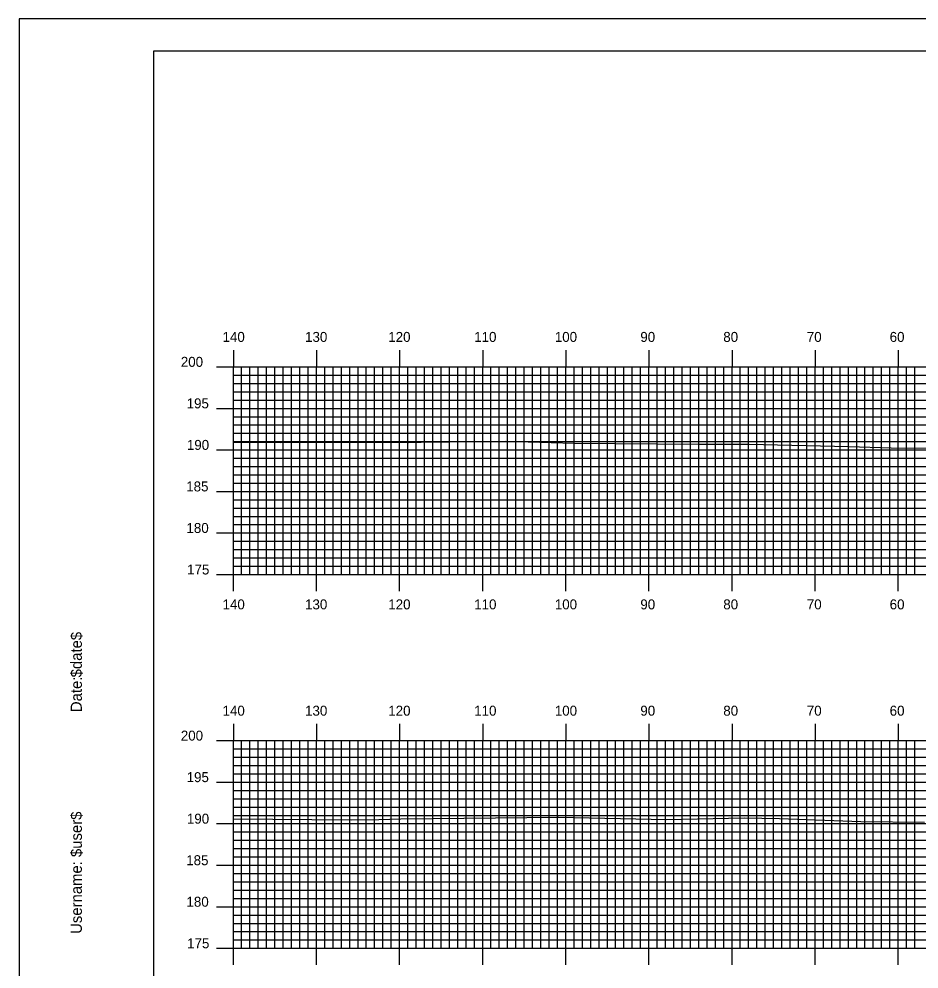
# Model space of a CAD drawing. Extents: x 1797994 to 1798337, y 442591 to 442811.
# Drawn here: x 1797994.2 to 1798102.5, y 442696.2 to 442810.5 of the extents above; entities that cross this region are included whole.
import ezdxf

# ---------------------------------------------------------------- set-up
doc = ezdxf.new("R2010")
doc.units = 0
for name, color, linetype in [('BORDER', 7, 'Continuous'), ('H_V ANNOTATION', 7, 'Continuous'), ('MAJOR', 7, 'Continuous'), ('MINOR', 7, 'Continuous'), ('PLOT BOUNDARY', 7, 'Continuous'), ('S_Roadway_Centerline', 7, 'Continuous')]:
    doc.layers.add(name, color=color, linetype=linetype)

msp = doc.modelspace()

# ---------------------------------------------------------------- linework, layer by layer
at = {"layer": 'BORDER'}
msp.add_lwpolyline([(1798010.36, 442596.67), (1798330.36, 442596.67), (1798330.36, 442806.67), (1798010.36, 442806.67)], close=True, dxfattribs=at)
at = {"layer": 'MAJOR'}
for p, q in [((1798019.96, 442770.67), (1798019.96, 442768.67)), ((1798029.96, 442770.67), (1798029.96, 442768.67)), ((1798039.96, 442770.67), (1798039.96, 442768.67)), ((1798049.96, 442770.67), (1798049.96, 442768.67)), ((1798059.96, 442770.67), (1798059.96, 442768.67)), ((1798069.96, 442770.67), (1798069.96, 442768.67)), ((1798079.96, 442770.67), (1798079.96, 442768.67)), ((1798089.96, 442770.67), (1798089.96, 442768.67)), ((1798099.96, 442770.67), (1798099.96, 442768.67)), ((1798017.95, 442768.67), (1798019.96, 442768.67)), ((1798019.96, 442768.67), (1798299.96, 442768.67)), ((1798019.96, 442743.67), (1798019.96, 442768.67)), ((1798019.96, 442743.67), (1798019.96, 442768.67)), ((1798019.96, 442768.67), (1798299.96, 442768.67)), ((1798029.96, 442743.67), (1798029.96, 442768.67)), ((1798039.96, 442743.67), (1798039.96, 442768.67)), ((1798049.96, 442743.67), (1798049.96, 442768.67)), ((1798059.96, 442743.67), (1798059.96, 442768.67)), ((1798069.96, 442743.67), (1798069.96, 442768.67)), ((1798079.96, 442743.67), (1798079.96, 442768.67)), ((1798089.96, 442743.67), (1798089.96, 442768.67)), ((1798099.96, 442743.67), (1798099.96, 442768.67)), ((1798017.95, 442763.67), (1798019.96, 442763.67)), ((1798019.96, 442763.67), (1798299.96, 442763.67)), ((1798017.95, 442758.67), (1798019.96, 442758.67)), ((1798019.96, 442758.67), (1798299.96, 442758.67)), ((1798017.95, 442753.67), (1798019.96, 442753.67)), ((1798019.96, 442753.67), (1798299.96, 442753.67)), ((1798017.95, 442748.67), (1798019.96, 442748.67)), ((1798019.96, 442748.67), (1798299.96, 442748.67)), ((1798017.95, 442743.67), (1798019.96, 442743.67)), ((1798019.96, 442743.67), (1798299.96, 442743.67)), ((1798019.96, 442743.67), (1798299.96, 442743.67)), ((1798019.96, 442741.66), (1798019.96, 442743.67)), ((1798029.96, 442741.66), (1798029.96, 442743.67)), ((1798039.96, 442741.66), (1798039.96, 442743.67)), ((1798049.96, 442741.66), (1798049.96, 442743.67)), ((1798059.96, 442741.66), (1798059.96, 442743.67)), ((1798069.96, 442741.66), (1798069.96, 442743.67)), ((1798079.96, 442741.66), (1798079.96, 442743.67)), ((1798089.96, 442741.66), (1798089.96, 442743.67)), ((1798099.96, 442741.66), (1798099.96, 442743.67)), ((1798019.96, 442725.67), (1798019.96, 442723.67)), ((1798029.96, 442725.67), (1798029.96, 442723.67)), ((1798039.96, 442725.67), (1798039.96, 442723.67)), ((1798049.96, 442725.67), (1798049.96, 442723.67)), ((1798059.96, 442725.67), (1798059.96, 442723.67)), ((1798069.96, 442725.67), (1798069.96, 442723.67)), ((1798079.96, 442725.67), (1798079.96, 442723.67)), ((1798089.96, 442725.67), (1798089.96, 442723.67)), ((1798099.96, 442725.67), (1798099.96, 442723.67)), ((1798017.95, 442723.67), (1798019.96, 442723.67)), ((1798019.96, 442723.67), (1798299.96, 442723.67)), ((1798019.96, 442698.67), (1798019.96, 442723.67)), ((1798019.96, 442698.67), (1798019.96, 442723.67)), ((1798019.96, 442723.67), (1798299.96, 442723.67)), ((1798029.96, 442698.67), (1798029.96, 442723.67)), ((1798039.96, 442698.67), (1798039.96, 442723.67)), ((1798049.96, 442698.67), (1798049.96, 442723.67)), ((1798059.96, 442698.67), (1798059.96, 442723.67)), ((1798069.96, 442698.67), (1798069.96, 442723.67)), ((1798079.96, 442698.67), (1798079.96, 442723.67)), ((1798089.96, 442698.67), (1798089.96, 442723.67)), ((1798099.96, 442698.67), (1798099.96, 442723.67)), ((1798017.95, 442718.67), (1798019.96, 442718.67)), ((1798019.96, 442718.67), (1798299.96, 442718.67)), ((1798017.95, 442713.67), (1798019.96, 442713.67)), ((1798019.96, 442713.67), (1798299.96, 442713.67)), ((1798017.95, 442708.67), (1798019.96, 442708.67)), ((1798019.96, 442708.67), (1798299.96, 442708.67)), ((1798017.95, 442703.67), (1798019.96, 442703.67)), ((1798019.96, 442703.67), (1798299.96, 442703.67)), ((1798017.95, 442698.67), (1798019.96, 442698.67)), ((1798019.96, 442698.67), (1798299.96, 442698.67)), ((1798019.96, 442698.67), (1798299.96, 442698.67)), ((1798019.96, 442696.66), (1798019.96, 442698.67)), ((1798029.96, 442696.66), (1798029.96, 442698.67)), ((1798039.96, 442696.66), (1798039.96, 442698.67)), ((1798049.96, 442696.66), (1798049.96, 442698.67)), ((1798059.96, 442696.66), (1798059.96, 442698.67)), ((1798069.96, 442696.66), (1798069.96, 442698.67)), ((1798079.96, 442696.66), (1798079.96, 442698.67)), ((1798089.96, 442696.66), (1798089.96, 442698.67)), ((1798099.96, 442696.66), (1798099.96, 442698.67))]:
    msp.add_line(p, q, dxfattribs=at)
at = {"layer": 'MINOR'}
for p, q in [((1798019.96, 442767.67), (1798299.96, 442767.67)), ((1798019.96, 442767.67), (1798021.96, 442767.67)), ((1798020.96, 442743.67), (1798020.96, 442768.67)), ((1798021.96, 442743.67), (1798021.96, 442768.67)), ((1798022.96, 442743.67), (1798022.96, 442768.67)), ((1798023.96, 442743.67), (1798023.96, 442768.67)), ((1798024.96, 442743.67), (1798024.96, 442768.67)), ((1798025.96, 442743.67), (1798025.96, 442768.67)), ((1798026.96, 442743.67), (1798026.96, 442768.67)), ((1798027.96, 442743.67), (1798027.96, 442768.67)), ((1798028.96, 442743.67), (1798028.96, 442768.67)), ((1798030.96, 442743.67), (1798030.96, 442768.67)), ((1798031.96, 442743.67), (1798031.96, 442768.67)), ((1798032.96, 442743.67), (1798032.96, 442768.67)), ((1798033.96, 442743.67), (1798033.96, 442768.67)), ((1798034.96, 442743.67), (1798034.96, 442768.67)), ((1798035.96, 442743.67), (1798035.96, 442768.67)), ((1798036.96, 442743.67), (1798036.96, 442768.67)), ((1798037.96, 442743.67), (1798037.96, 442768.67)), ((1798038.96, 442743.67), (1798038.96, 442768.67)), ((1798040.96, 442743.67), (1798040.96, 442768.67)), ((1798041.96, 442743.67), (1798041.96, 442768.67)), ((1798042.96, 442743.67), (1798042.96, 442768.67)), ((1798043.96, 442743.67), (1798043.96, 442768.67)), ((1798044.96, 442743.67), (1798044.96, 442768.67)), ((1798045.96, 442743.67), (1798045.96, 442768.67)), ((1798046.96, 442743.67), (1798046.96, 442768.67)), ((1798047.96, 442743.67), (1798047.96, 442768.67)), ((1798048.96, 442743.67), (1798048.96, 442768.67)), ((1798050.96, 442743.67), (1798050.96, 442768.67)), ((1798051.96, 442743.67), (1798051.96, 442768.67)), ((1798052.96, 442743.67), (1798052.96, 442768.67)), ((1798053.96, 442743.67), (1798053.96, 442768.67)), ((1798054.96, 442743.67), (1798054.96, 442768.67)), ((1798055.96, 442743.67), (1798055.96, 442768.67)), ((1798056.96, 442743.67), (1798056.96, 442768.67)), ((1798057.96, 442743.67), (1798057.96, 442768.67)), ((1798058.96, 442743.67), (1798058.96, 442768.67)), ((1798060.96, 442743.67), (1798060.96, 442768.67)), ((1798061.96, 442743.67), (1798061.96, 442768.67)), ((1798062.96, 442743.67), (1798062.96, 442768.67)), ((1798063.96, 442743.67), (1798063.96, 442768.67)), ((1798064.96, 442743.67), (1798064.96, 442768.67)), ((1798065.96, 442743.67), (1798065.96, 442768.67)), ((1798066.96, 442743.67), (1798066.96, 442768.67)), ((1798067.96, 442743.67), (1798067.96, 442768.67)), ((1798068.96, 442743.67), (1798068.96, 442768.67)), ((1798070.96, 442743.67), (1798070.96, 442768.67)), ((1798071.96, 442743.67), (1798071.96, 442768.67)), ((1798072.96, 442743.67), (1798072.96, 442768.67)), ((1798073.96, 442743.67), (1798073.96, 442768.67)), ((1798074.96, 442743.67), (1798074.96, 442768.67)), ((1798075.96, 442743.67), (1798075.96, 442768.67)), ((1798076.96, 442743.67), (1798076.96, 442768.67)), ((1798077.96, 442743.67), (1798077.96, 442768.67)), ((1798078.96, 442743.67), (1798078.96, 442768.67)), ((1798080.96, 442743.67), (1798080.96, 442768.67)), ((1798081.96, 442743.67), (1798081.96, 442768.67)), ((1798082.96, 442743.67), (1798082.96, 442768.67)), ((1798083.96, 442743.67), (1798083.96, 442768.67)), ((1798084.96, 442743.67), (1798084.96, 442768.67)), ((1798085.96, 442743.67), (1798085.96, 442768.67)), ((1798086.96, 442743.67), (1798086.96, 442768.67)), ((1798087.96, 442743.67), (1798087.96, 442768.67)), ((1798088.96, 442743.67), (1798088.96, 442768.67)), ((1798090.96, 442743.67), (1798090.96, 442768.67)), ((1798091.96, 442743.67), (1798091.96, 442768.67)), ((1798092.96, 442743.67), (1798092.96, 442768.67)), ((1798093.96, 442743.67), (1798093.96, 442768.67)), ((1798094.96, 442743.67), (1798094.96, 442768.67)), ((1798095.96, 442743.67), (1798095.96, 442768.67)), ((1798096.96, 442743.67), (1798096.96, 442768.67)), ((1798097.96, 442743.67), (1798097.96, 442768.67)), ((1798098.96, 442743.67), (1798098.96, 442768.67)), ((1798100.96, 442743.67), (1798100.96, 442768.67)), ((1798101.96, 442743.67), (1798101.96, 442768.67)), ((1798019.96, 442766.67), (1798299.96, 442766.67)), ((1798019.96, 442766.67), (1798021.96, 442766.67)), ((1798019.96, 442765.67), (1798299.96, 442765.67)), ((1798019.96, 442765.67), (1798021.96, 442765.67)), ((1798019.96, 442764.67), (1798299.96, 442764.67)), ((1798019.96, 442764.67), (1798021.96, 442764.67)), ((1798019.96, 442762.67), (1798299.96, 442762.67)), ((1798019.96, 442762.67), (1798021.96, 442762.67)), ((1798019.96, 442761.67), (1798299.96, 442761.67)), ((1798019.96, 442761.67), (1798021.96, 442761.67)), ((1798019.96, 442760.67), (1798299.96, 442760.67)), ((1798019.96, 442760.67), (1798021.96, 442760.67)), ((1798019.96, 442759.67), (1798299.96, 442759.67)), ((1798019.96, 442759.67), (1798021.96, 442759.67)), ((1798019.96, 442757.67), (1798299.96, 442757.67)), ((1798019.96, 442757.67), (1798021.96, 442757.67)), ((1798019.96, 442756.67), (1798299.96, 442756.67)), ((1798019.96, 442756.67), (1798021.96, 442756.67)), ((1798019.96, 442755.67), (1798299.96, 442755.67)), ((1798019.96, 442755.67), (1798021.96, 442755.67)), ((1798019.96, 442754.67), (1798299.96, 442754.67)), ((1798019.96, 442754.67), (1798021.96, 442754.67)), ((1798019.96, 442752.67), (1798299.96, 442752.67)), ((1798019.96, 442752.67), (1798021.96, 442752.67)), ((1798019.96, 442751.67), (1798299.96, 442751.67)), ((1798019.96, 442751.67), (1798021.96, 442751.67)), ((1798019.96, 442750.67), (1798299.96, 442750.67)), ((1798019.96, 442750.67), (1798021.96, 442750.67)), ((1798019.96, 442749.67), (1798299.96, 442749.67)), ((1798019.96, 442749.67), (1798021.96, 442749.67)), ((1798019.96, 442747.67), (1798299.96, 442747.67)), ((1798019.96, 442747.67), (1798021.96, 442747.67)), ((1798019.96, 442746.67), (1798299.96, 442746.67)), ((1798019.96, 442746.67), (1798021.96, 442746.67)), ((1798019.96, 442745.67), (1798299.96, 442745.67)), ((1798019.96, 442745.67), (1798021.96, 442745.67)), ((1798019.96, 442744.67), (1798299.96, 442744.67)), ((1798019.96, 442744.67), (1798021.96, 442744.67)), ((1798020.96, 442698.67), (1798020.96, 442723.67)), ((1798021.96, 442698.67), (1798021.96, 442723.67)), ((1798022.96, 442698.67), (1798022.96, 442723.67)), ((1798023.96, 442698.67), (1798023.96, 442723.67)), ((1798024.96, 442698.67), (1798024.96, 442723.67)), ((1798025.96, 442698.67), (1798025.96, 442723.67)), ((1798026.96, 442698.67), (1798026.96, 442723.67)), ((1798027.96, 442698.67), (1798027.96, 442723.67)), ((1798028.96, 442698.67), (1798028.96, 442723.67)), ((1798030.96, 442698.67), (1798030.96, 442723.67)), ((1798031.96, 442698.67), (1798031.96, 442723.67)), ((1798032.96, 442698.67), (1798032.96, 442723.67)), ((1798033.96, 442698.67), (1798033.96, 442723.67)), ((1798034.96, 442698.67), (1798034.96, 442723.67)), ((1798035.96, 442698.67), (1798035.96, 442723.67)), ((1798036.96, 442698.67), (1798036.96, 442723.67)), ((1798037.96, 442698.67), (1798037.96, 442723.67)), ((1798038.96, 442698.67), (1798038.96, 442723.67)), ((1798040.96, 442698.67), (1798040.96, 442723.67)), ((1798041.96, 442698.67), (1798041.96, 442723.67)), ((1798042.96, 442698.67), (1798042.96, 442723.67)), ((1798043.96, 442698.67), (1798043.96, 442723.67)), ((1798044.96, 442698.67), (1798044.96, 442723.67)), ((1798045.96, 442698.67), (1798045.96, 442723.67)), ((1798046.96, 442698.67), (1798046.96, 442723.67)), ((1798047.96, 442698.67), (1798047.96, 442723.67)), ((1798048.96, 442698.67), (1798048.96, 442723.67)), ((1798050.96, 442698.67), (1798050.96, 442723.67)), ((1798051.96, 442698.67), (1798051.96, 442723.67)), ((1798052.96, 442698.67), (1798052.96, 442723.67)), ((1798053.96, 442698.67), (1798053.96, 442723.67)), ((1798054.96, 442698.67), (1798054.96, 442723.67)), ((1798055.96, 442698.67), (1798055.96, 442723.67)), ((1798056.96, 442698.67), (1798056.96, 442723.67)), ((1798057.96, 442698.67), (1798057.96, 442723.67)), ((1798058.96, 442698.67), (1798058.96, 442723.67)), ((1798060.96, 442698.67), (1798060.96, 442723.67)), ((1798061.96, 442698.67), (1798061.96, 442723.67)), ((1798062.96, 442698.67), (1798062.96, 442723.67)), ((1798063.96, 442698.67), (1798063.96, 442723.67)), ((1798064.96, 442698.67), (1798064.96, 442723.67)), ((1798065.96, 442698.67), (1798065.96, 442723.67)), ((1798066.96, 442698.67), (1798066.96, 442723.67)), ((1798067.96, 442698.67), (1798067.96, 442723.67)), ((1798068.96, 442698.67), (1798068.96, 442723.67)), ((1798070.96, 442698.67), (1798070.96, 442723.67)), ((1798071.96, 442698.67), (1798071.96, 442723.67)), ((1798072.96, 442698.67), (1798072.96, 442723.67)), ((1798073.96, 442698.67), (1798073.96, 442723.67)), ((1798074.96, 442698.67), (1798074.96, 442723.67)), ((1798075.96, 442698.67), (1798075.96, 442723.67)), ((1798076.96, 442698.67), (1798076.96, 442723.67)), ((1798077.96, 442698.67), (1798077.96, 442723.67)), ((1798078.96, 442698.67), (1798078.96, 442723.67)), ((1798080.96, 442698.67), (1798080.96, 442723.67)), ((1798081.96, 442698.67), (1798081.96, 442723.67)), ((1798082.96, 442698.67), (1798082.96, 442723.67)), ((1798083.96, 442698.67), (1798083.96, 442723.67)), ((1798084.96, 442698.67), (1798084.96, 442723.67)), ((1798085.96, 442698.67), (1798085.96, 442723.67)), ((1798086.96, 442698.67), (1798086.96, 442723.67)), ((1798087.96, 442698.67), (1798087.96, 442723.67)), ((1798088.96, 442698.67), (1798088.96, 442723.67)), ((1798090.96, 442698.67), (1798090.96, 442723.67)), ((1798091.96, 442698.67), (1798091.96, 442723.67)), ((1798092.96, 442698.67), (1798092.96, 442723.67)), ((1798093.96, 442698.67), (1798093.96, 442723.67)), ((1798094.96, 442698.67), (1798094.96, 442723.67)), ((1798095.96, 442698.67), (1798095.96, 442723.67)), ((1798096.96, 442698.67), (1798096.96, 442723.67)), ((1798097.96, 442698.67), (1798097.96, 442723.67)), ((1798098.96, 442698.67), (1798098.96, 442723.67)), ((1798100.96, 442698.67), (1798100.96, 442723.67)), ((1798101.96, 442698.67), (1798101.96, 442723.67)), ((1798019.96, 442722.67), (1798299.96, 442722.67)), ((1798019.96, 442722.67), (1798021.96, 442722.67)), ((1798019.96, 442721.67), (1798299.96, 442721.67)), ((1798019.96, 442721.67), (1798021.96, 442721.67)), ((1798019.96, 442720.67), (1798299.96, 442720.67)), ((1798019.96, 442720.67), (1798021.96, 442720.67)), ((1798019.96, 442719.67), (1798299.96, 442719.67)), ((1798019.96, 442719.67), (1798021.96, 442719.67)), ((1798019.96, 442717.67), (1798299.96, 442717.67)), ((1798019.96, 442717.67), (1798021.96, 442717.67)), ((1798019.96, 442716.67), (1798299.96, 442716.67)), ((1798019.96, 442716.67), (1798021.96, 442716.67)), ((1798019.96, 442715.67), (1798299.96, 442715.67)), ((1798019.96, 442715.67), (1798021.96, 442715.67)), ((1798019.96, 442714.67), (1798299.96, 442714.67)), ((1798019.96, 442714.67), (1798021.96, 442714.67)), ((1798019.96, 442712.67), (1798299.96, 442712.67)), ((1798019.96, 442712.67), (1798021.96, 442712.67)), ((1798019.96, 442711.67), (1798299.96, 442711.67)), ((1798019.96, 442711.67), (1798021.96, 442711.67)), ((1798019.96, 442710.67), (1798299.96, 442710.67)), ((1798019.96, 442710.67), (1798021.96, 442710.67)), ((1798019.96, 442709.67), (1798299.96, 442709.67)), ((1798019.96, 442709.67), (1798021.96, 442709.67)), ((1798019.96, 442707.67), (1798299.96, 442707.67)), ((1798019.96, 442707.67), (1798021.96, 442707.67)), ((1798019.96, 442706.67), (1798299.96, 442706.67)), ((1798019.96, 442706.67), (1798021.96, 442706.67)), ((1798019.96, 442705.67), (1798299.96, 442705.67)), ((1798019.96, 442705.67), (1798021.96, 442705.67)), ((1798019.96, 442704.67), (1798299.96, 442704.67)), ((1798019.96, 442704.67), (1798021.96, 442704.67)), ((1798019.96, 442702.67), (1798299.96, 442702.67)), ((1798019.96, 442702.67), (1798021.96, 442702.67)), ((1798019.96, 442701.67), (1798299.96, 442701.67)), ((1798019.96, 442701.67), (1798021.96, 442701.67)), ((1798019.96, 442700.67), (1798299.96, 442700.67)), ((1798019.96, 442700.67), (1798021.96, 442700.67)), ((1798019.96, 442699.67), (1798299.96, 442699.67)), ((1798019.96, 442699.67), (1798021.96, 442699.67))]:
    msp.add_line(p, q, dxfattribs=at)
at = {"layer": 'PLOT BOUNDARY'}
msp.add_lwpolyline([(1797994.17, 442590.55), (1798334.17, 442590.55), (1798334.17, 442810.55), (1797994.17, 442810.55)], close=True, dxfattribs=at)
at = {"layer": 'S_Roadway_Centerline'}
for points in [[(1798019.96, 442759.59), (1798025.6, 442759.57), (1798039.68, 442759.58), (1798041.05, 442759.56), (1798042.55, 442759.58), (1798052.68, 442759.72), (1798060.98, 442759.49), (1798075.9, 442759.37), (1798082.04, 442759.36), (1798094.02, 442759.06), (1798099.12, 442758.93), (1798104.44, 442758.87)], [(1798019.96, 442714.27), (1798034.15, 442714.14), (1798037.48, 442714.16), (1798040.1, 442714.26), (1798059.07, 442714.46), (1798059.11, 442714.47), (1798059.12, 442714.47), (1798072.08, 442714.18), (1798081.44, 442714.39), (1798085.68, 442714.3), (1798095.45, 442713.94), (1798103.11, 442713.87)]]:
    msp.add_lwpolyline(points, dxfattribs=at)

# ---------------------------------------------------------------- texts
at = {"layer": 'BORDER'}
for s, p in [('$date$', (1798001.73, 442731.28)), ('Date:', (1798001.73, 442727.1)), ('$user$', (1798001.73, 442709.65)), ('Username:', (1798001.73, 442700.4))]:
    msp.add_text(s, height=1.339, rotation=90, dxfattribs=at).set_placement(p)
at = {"layer": 'H_V ANNOTATION'}
for s, p in [('140', (1798018.66, 442771.67)), ('130', (1798028.59, 442771.67)), ('120', (1798038.6, 442771.67)), ('110', (1798048.94, 442771.67)), ('100', (1798058.64, 442771.67)), ('90', (1798068.93, 442771.67)), ('80', (1798078.91, 442771.67)), ('70', (1798088.96, 442771.67)), ('60', (1798098.93, 442771.67)), ('200', (1798013.64, 442768.67)), ('195', (1798014.34, 442763.67)), ('190', (1798014.37, 442758.67)), ('185', (1798014.29, 442753.67)), ('180', (1798014.32, 442748.67)), ('175', (1798014.4, 442743.67)), ('140', (1798018.66, 442739.47)), ('130', (1798028.59, 442739.47)), ('120', (1798038.6, 442739.47)), ('110', (1798048.94, 442739.47)), ('100', (1798058.64, 442739.47)), ('90', (1798068.93, 442739.47)), ('80', (1798078.91, 442739.47)), ('70', (1798088.96, 442739.47)), ('60', (1798098.93, 442739.47)), ('140', (1798018.66, 442726.67)), ('130', (1798028.59, 442726.67)), ('120', (1798038.6, 442726.67)), ('110', (1798048.94, 442726.67)), ('100', (1798058.64, 442726.67)), ('90', (1798068.93, 442726.67)), ('80', (1798078.91, 442726.67)), ('70', (1798088.96, 442726.67)), ('60', (1798098.93, 442726.67)), ('200', (1798013.64, 442723.67)), ('195', (1798014.34, 442718.67)), ('190', (1798014.37, 442713.67)), ('185', (1798014.29, 442708.67)), ('180', (1798014.32, 442703.67)), ('175', (1798014.4, 442698.67))]:
    msp.add_text(s, height=1.2, dxfattribs=at).set_placement(p)
at = {"layer": 'MAJOR'}
for p in [(1798019.95, 442743.67), (1798019.95, 442698.67)]:
    msp.add_text('-', height=0.012, dxfattribs=at).set_placement(p)

doc.saveas('drawing.dxf')
